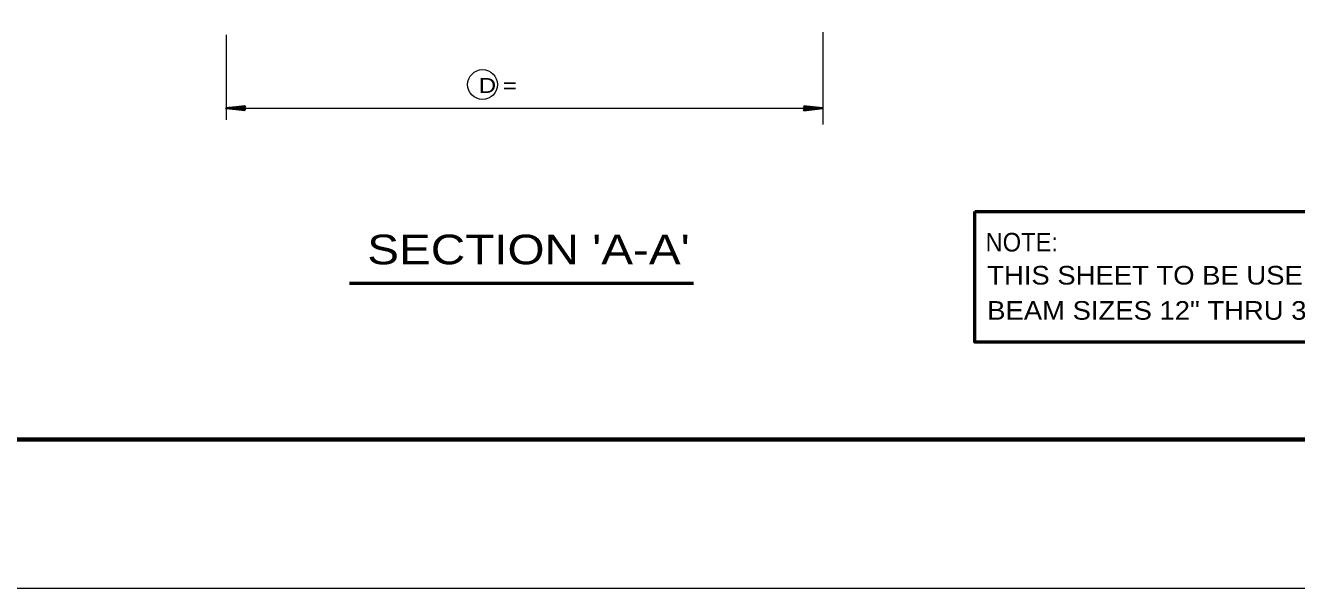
# Model space of a CAD drawing. Extents: x 4.49 to 7.69, y 0.28 to 2.27.
# Drawn here: x 5.742 to 6.452, y 0.283 to 0.598 of the extents above; entities that cross this region are included whole.
import ezdxf

# ---------------------------------------------------------------- set-up
doc = ezdxf.new("R2010")
doc.units = 0
doc.header["$LTSCALE"] = 0.0033
doc.layers.add('1', color=7, linetype='Continuous', lineweight=35)

msp = doc.modelspace()

# ---------------------------------------------------------------- linework, layer by layer
at = {"layer": '1', "lineweight": 13}
for p, q in [((5.854417, 0.592333), (5.854417, 0.544917)), ((6.18775, 0.593833), (6.18775, 0.542167)), ((5.8545, 0.551333), (6.187833, 0.551333)), ((7.689167, 0.28275), (4.492417, 0.28275))]:
    msp.add_line(p, q, dxfattribs=at)
at = {"layer": '1'}
for p, q in [((5.865, 0.551333), (5.854417, 0.551333)), ((5.86475, 0.5505), (5.856917, 0.5515)), ((5.86475, 0.5505), (5.856917, 0.551333)), ((5.86475, 0.550333), (5.856917, 0.55125)), ((5.86475, 0.550333), (5.856917, 0.55125)), ((5.86475, 0.550417), (5.856917, 0.55125)), ((5.86475, 0.552417), (5.857417, 0.551583)), ((5.86475, 0.55225), (5.857417, 0.5515)), ((5.86475, 0.552167), (5.857417, 0.551333)), ((5.864833, 0.552), (5.8575, 0.55125)), ((6.177167, 0.551333), (6.18775, 0.551333)), ((6.177333, 0.550667), (6.184667, 0.551417)), ((6.177417, 0.552333), (6.18525, 0.551417)), ((6.177417, 0.552333), (6.18525, 0.551417)), ((6.177417, 0.55225), (6.18525, 0.551417)), ((6.177417, 0.552167), (6.18525, 0.551333)), ((6.177417, 0.552167), (6.18525, 0.551167)), ((6.177417, 0.5505), (6.18475, 0.551333)), ((6.177417, 0.550417), (6.18475, 0.551167)), ((6.177417, 0.55025), (6.18475, 0.551083))]:
    msp.add_line(p, q, dxfattribs=at)
at = {"layer": '1', "lineweight": 53}
msp.add_line((5.92325, 0.453583), (6.115583, 0.453583), dxfattribs=at)
at = {"layer": '1', "lineweight": 70}
msp.add_line((4.659167, 0.366083), (7.605833, 0.366083), dxfattribs=at)
at = {"layer": '1', "lineweight": 40}
msp.add_lwpolyline([(4.659167, 0.366083), (7.020833, 0.366083), (7.020833, 0.691167), (7.605833, 0.691167)], dxfattribs=at)
at = {"layer": '1'}
for points in [[(5.865, 0.55025), (5.854417, 0.551333), (5.865, 0.5525), (5.864417, 0.551333)], [(5.86425, 0.55125), (5.859583, 0.551167), (5.859583, 0.55125), (5.8605, 0.55125), (5.86425, 0.551167), (5.86125, 0.551083), (5.864417, 0.551), (5.862167, 0.550917), (5.864417, 0.550833), (5.860917, 0.551083), (5.85625, 0.55125), (5.857167, 0.5515), (5.855917, 0.5515), (5.86425, 0.5515), (5.861833, 0.551667), (5.864417, 0.551667), (5.859083, 0.55125), (5.864417, 0.551917)], [(6.177167, 0.552417), (6.18775, 0.551333), (6.177167, 0.550167), (6.17775, 0.551333)], [(6.177917, 0.551417), (6.182583, 0.5515), (6.182583, 0.551417), (6.181667, 0.551417), (6.177917, 0.5515), (6.180917, 0.551583), (6.17775, 0.551667), (6.18, 0.55175), (6.17775, 0.551833), (6.18125, 0.551583), (6.185917, 0.551417), (6.185, 0.551167), (6.18625, 0.551167), (6.177917, 0.551167), (6.180333, 0.551), (6.17775, 0.551), (6.183083, 0.551417), (6.17775, 0.55075)]]:
    msp.add_lwpolyline(points, close=True, dxfattribs=at)
for points in [[(5.86425, 0.55125), (5.864667, 0.5505), (5.864417, 0.55075), (5.86425, 0.551083), (5.864, 0.551), (5.864167, 0.550667), (5.864333, 0.551417), (5.8645, 0.551917), (5.86475, 0.552333)], [(6.177917, 0.551417), (6.1775, 0.552167), (6.17775, 0.551917), (6.177917, 0.551583), (6.178167, 0.551667), (6.178, 0.552), (6.177833, 0.55125), (6.177667, 0.55075), (6.177417, 0.550333)]]:
    msp.add_lwpolyline(points, dxfattribs=at)
at = {"layer": '1', "lineweight": 53}
msp.add_lwpolyline([(6.272583, 0.493667), (6.521833, 0.493667), (6.521833, 0.4205), (6.272583, 0.4205)], close=True, dxfattribs=at)
at = {"layer": '1', "lineweight": 13}
msp.add_circle((5.997667, 0.564583), 0.008333, dxfattribs=at)

# ---------------------------------------------------------------- texts
at = {"layer": '1'}
for s, height, width, p in [('D =      ', 0.008334, 1.2, (5.995583, 0.559917)), ("SECTION 'A-A'", 0.01658, 1.2, (5.93325, 0.464083)), ('NOTE:', 0.01042, 0.95, (6.278667, 0.47125)), ('THIS SHEET TO BE USED WITH', 0.01042, 1.1, (6.279583, 0.45275)), ('BEAM SIZES 12" THRU 33" ONLY.', 0.01042, 1.1, (6.279583, 0.433083))]:
    msp.add_text(s, height=height, dxfattribs=dict(at, width=width)).set_placement(p)

doc.saveas('drawing.dxf')
